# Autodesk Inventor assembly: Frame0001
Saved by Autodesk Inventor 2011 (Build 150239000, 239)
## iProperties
Created: 2020-12
Part Number: Frame0001
Document SubType Name: Assembly
Designer: PC
_FrameDoc: Frame Assembly
_Version: 15.0.0
Author: PC
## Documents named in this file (6)
- C:\Users\PC\Documents\Inventor\workshop-crane-powered-by-drill\4_pata-izquierda\Frame\Frame0001.iam
- C:\Users\PC\Documents\Inventor\workshop-crane-powered-by-drill\4_pata-izquierda\Frame\Skeleton0001.ipt
- C:\Users\PC\Documents\Inventor\workshop-crane-powered-by-drill\4_pata-izquierda\Frame\DIN 50 x 50 x 4 00000002.ipt
- DIN 50 x 50 x 4 00000002.ipt
- C:\Users\PC\Documents\Inventor\workshop-crane-powered-by-drill\4_pata-izquierda\Frame\DIN 50 x 12 00000003.ipt
- DIN 50 x 12 00000003.ipt
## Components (3 placed, 3 different names)
1. Frame Reference Model
2. DIN 50 x 50 x 4 00000002:1
3. DIN 50 x 12 00000003:1
